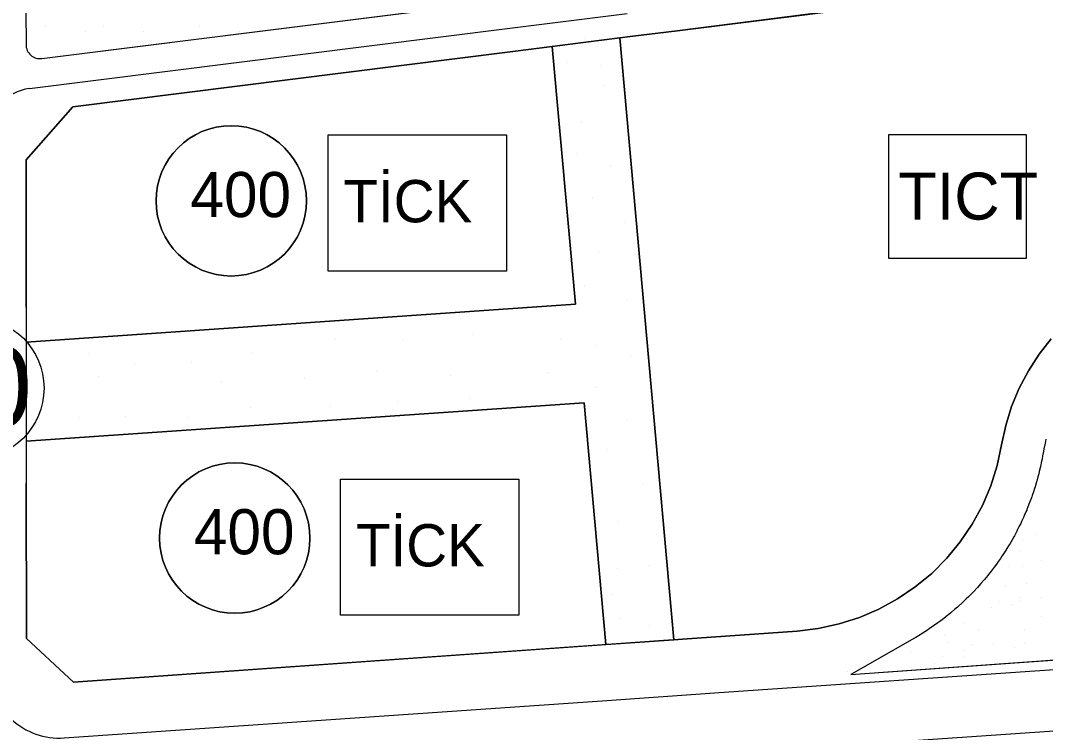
# Model space of a CAD drawing. Extents: x 419109 to 421295, y 4452223 to 4457798.
# Drawn here: x 419811.7 to 420029.7, y 4453711.7 to 4453863.1 of the extents above; entities that cross this region are included whole.
import ezdxf

# ---------------------------------------------------------------- set-up
doc = ezdxf.new("R2010")
doc.units = 0
for name, color, linetype in [('ADA', 7, 'Continuous'), ('ADAKENARI', 7, 'Continuous'), ('Default', 7, 'Continuous'), ('KALDIRIM', 7, 'Continuous'), ('KD_DAIRE', 7, 'Continuous'), ('KD_YGEN', 7, 'Continuous'), ('LJ_SEMBOL', 7, 'Continuous'), ('PL_AYA_PARK_DINLENME', 7, 'Continuous'), ('PL_TİCK', 7, 'Continuous'), ('PL_TURZM', 7, 'Continuous'), ('SM_TAKS', 7, 'Continuous'), ('TR_PARKALANI', 7, 'Continuous'), ('TR_TİCK', 7, 'Continuous'), ('TR_TİCT', 7, 'Continuous')]:
    doc.layers.add(name, color=color, linetype=linetype)

# ---------------------------------------------------------------- blocks, each defined once
blk = doc.blocks.new('POINT_DISPLAY')
at = {"layer": 'Default'}
blk.add_line((0, 0), (0, 0), dxfattribs=at)

msp = doc.modelspace()

# ---------------------------------------------------------------- linework, layer by layer
at = {"layer": 'ADA'}
for p, q in [((419924.74, 4453857.56), (419929.68, 4453802.74)), ((419950.66, 4453731.4), (419939.14, 4453859.37)), ((419931.56, 4453781.8), (419936.2, 4453730.38))]:
    msp.add_line(p, q, dxfattribs=at)
at = {"layer": 'ADAKENARI'}
for p, q in [((419951.35, 4453860.91), (420102.08, 4453879.87)), ((419816.2, 4453855), (419926.11, 4453868.82)), ((419812.82, 4453865.02), (419812.83, 4453857.97)), ((419941.35, 4453859.65), (419951.35, 4453860.91)), ((419915.81, 4453856.44), (419941.35, 4453859.65)), ((419822.76, 4453844.73), (419915.81, 4453856.44)), ((419812.84, 4453833.49), (419822.76, 4453844.73)), ((419812.87, 4453802.15), (419812.84, 4453833.49)), ((419812.87, 4453794.67), (419929.68, 4453802.74)), ((419812.87, 4453802.15), (419812.89, 4453764.59)), ((420030.92, 4453795.41), (420028.33, 4453792.11)), ((420028.33, 4453792.11), (420026.04, 4453788.58)), ((420026.04, 4453788.58), (420024.09, 4453784.87)), ((420024.09, 4453784.87), (420022.48, 4453780.99)), ((419812.89, 4453773.6), (419931.56, 4453781.8)), ((420022.48, 4453780.99), (420021.24, 4453776.98)), ((420021.24, 4453776.98), (420020.36, 4453772.87)), ((420020.36, 4453772.87), (420019.41, 4453768.44)), ((420019.41, 4453768.44), (420018.04, 4453764.12)), ((419812.92, 4453731.68), (419812.89, 4453764.59)), ((420018.04, 4453764.12), (420016.26, 4453759.95)), ((420016.26, 4453759.95), (420014.09, 4453755.97)), ((420014.09, 4453755.97), (420011.56, 4453752.21)), ((420011.56, 4453752.21), (420008.68, 4453748.72)), ((420008.68, 4453748.72), (420005.48, 4453745.51)), ((420005.48, 4453745.51), (420001.98, 4453742.62)), ((420001.98, 4453742.62), (419998.23, 4453740.08)), ((419998.23, 4453740.08), (419994.25, 4453737.91)), ((419994.25, 4453737.91), (419990.09, 4453736.13)), ((419990.09, 4453736.13), (419985.77, 4453734.75)), ((419976.84, 4453733.25), (419952.49, 4453731.53)), ((419981.34, 4453733.79), (419976.84, 4453733.25)), ((419985.77, 4453734.75), (419981.34, 4453733.79)), ((419812.92, 4453731.68), (419822.9, 4453722.39)), ((419952.49, 4453731.53), (419822.9, 4453722.39))]:
    msp.add_line(p, q, dxfattribs=at)
msp.add_arc((419815.83, 4453857.97), 3, 180.035, 277.1691, dxfattribs=at)
at = {"layer": 'KALDIRIM'}
for p, q in [((419915.19, 4453861.4), (419940.72, 4453864.61)), ((419813.59, 4453848.62), (419915.19, 4453861.4)), ((419960.3, 4453720.14), (420172.91, 4453734.83)), ((419988.28, 4453724.03), (420064.1, 4453729.39)), ((419961.31, 4453707.18), (420174.53, 4453721.91)), ((419820.96, 4453710.51), (419935.36, 4453718.41)), ((419935.36, 4453718.41), (419960.3, 4453720.14))]:
    msp.add_line(p, q, dxfattribs=at)
msp.add_lwpolyline([(420029.78, 4453774.04), (420029.68, 4453773.61), (420029.59, 4453773.22), (420029.44, 4453772.51), (420029.42, 4453772.38), (420029.26, 4453771.55), (420029.24, 4453771.4), (420029.08, 4453770.48), (420028.95, 4453769.82), (420028.87, 4453769.37), (420028.63, 4453768.27), (420028.62, 4453768.24), (420028.37, 4453767.17), (420028.25, 4453766.68), (420028.09, 4453766.07), (420027.83, 4453765.13), (420027.79, 4453764.98), (420027.46, 4453763.9), (420027.37, 4453763.59), (420027.12, 4453762.82), (420026.86, 4453762.07), (420026.75, 4453761.76), (420026.36, 4453760.69), (420026.31, 4453760.56), (420025.95, 4453759.64), (420025.72, 4453759.07), (420025.68, 4453758.97), (420025.52, 4453758.6), (420025.09, 4453757.59), (420025.07, 4453757.56), (420024.6, 4453756.53), (420024.41, 4453756.13), (420024.11, 4453755.52), (420023.69, 4453754.7), (420023.6, 4453754.51), (420023.06, 4453753.51), (420022.94, 4453753.28), (420022.51, 4453752.53), (420022.14, 4453751.89), (420021.94, 4453751.55), (420021.35, 4453750.59), (420021.3, 4453750.52), (420020.74, 4453749.64), (420020.5, 4453749.27), (420020.43, 4453749.17), (420020.11, 4453748.7), (420019.51, 4453747.85), (420019.46, 4453747.77), (420018.79, 4453746.86), (420018.56, 4453746.55), (420018.11, 4453745.96), (420017.58, 4453745.29), (420017.41, 4453745.08), (420016.69, 4453744.21), (420016.55, 4453744.05), (420015.95, 4453743.35), (420015.5, 4453742.84), (420015.2, 4453742.51), (420014.43, 4453741.68), (420014.41, 4453741.66), (420013.64, 4453740.87), (420013.28, 4453740.51), (420012.84, 4453740.08), (420012.12, 4453739.4), (420012.02, 4453739.3), (420011.18, 4453738.54), (420010.94, 4453738.32), (420010.33, 4453737.79), (420009.72, 4453737.27), (420009.47, 4453737.06), (420008.59, 4453736.35), (420008.47, 4453736.26), (420007.7, 4453735.66), (420007.2, 4453735.28), (420006.79, 4453734.98), (420005.89, 4453734.34), (420005.87, 4453734.33), (420004.94, 4453733.69), (420004.56, 4453733.44), (420003.99, 4453733.07), (420003.21, 4453732.58), (420003.04, 4453732.47), (420002.07, 4453731.89), (420001.83, 4453731.75), (419988.28, 4453724.03)], dxfattribs=at)
for centre, radius, start, end in [((419814.84, 4453838.7), 10, 97.1689, 180.0425), ((419819.92, 4453725.47), 15, 180.0425, 273.9541)]:
    msp.add_arc(centre, radius, start, end, dxfattribs=at)
at = {"layer": 'KD_DAIRE'}
msp.add_circle((419801.66, 4453784.89), 15, dxfattribs=at)
at = {"layer": 'LJ_SEMBOL'}
for points in [[(419877.07, 4453838.74), (419915.01, 4453838.74), (419915.01, 4453809.8), (419877.07, 4453809.8)], [(419996.37, 4453838.81), (420025.57, 4453838.81), (420025.57, 4453812.46), (419996.37, 4453812.46)], [(419879.75, 4453765.56), (419917.68, 4453765.56), (419917.68, 4453736.62), (419879.75, 4453736.62)]]:
    msp.add_lwpolyline(points, close=True, dxfattribs=at)
at = {"layer": 'PL_AYA_PARK_DINLENME'}
for points in [[(419816.2, 4453855), (419926.11, 4453868.82), (419942, 4453870.82), (419977.82, 4453875.32)], [(419812.82, 4453865.02), (419812.83, 4453857.97)], [(419936.2, 4453730.38), (419950.66, 4453731.4), (419939.14, 4453859.37), (419924.74, 4453857.56), (419929.68, 4453802.74), (419812.87, 4453794.67), (419812.89, 4453773.6), (419931.56, 4453781.8), (419936.2, 4453730.38)], [(420029.78, 4453774.04), (420029.68, 4453773.61), (420029.59, 4453773.22), (420029.44, 4453772.51), (420029.42, 4453772.38), (420029.26, 4453771.55), (420029.24, 4453771.4), (420029.08, 4453770.48), (420028.95, 4453769.82), (420028.87, 4453769.37), (420028.63, 4453768.27), (420028.62, 4453768.24), (420028.37, 4453767.17), (420028.25, 4453766.68), (420028.09, 4453766.07), (420027.83, 4453765.13), (420027.79, 4453764.98), (420027.46, 4453763.9), (420027.37, 4453763.59), (420027.12, 4453762.82), (420026.86, 4453762.07), (420026.75, 4453761.76), (420026.36, 4453760.69), (420026.31, 4453760.56), (420025.95, 4453759.64), (420025.72, 4453759.07), (420025.68, 4453758.97), (420025.52, 4453758.6), (420025.09, 4453757.59), (420025.07, 4453757.56), (420024.6, 4453756.53), (420024.41, 4453756.13), (420024.11, 4453755.52), (420023.69, 4453754.7), (420023.6, 4453754.51), (420023.06, 4453753.51), (420022.94, 4453753.28), (420022.51, 4453752.53), (420022.14, 4453751.89), (420021.94, 4453751.55), (420021.35, 4453750.59), (420021.3, 4453750.52), (420020.74, 4453749.64), (420020.5, 4453749.27), (420020.43, 4453749.17), (420020.11, 4453748.7), (420019.51, 4453747.85), (420019.46, 4453747.77), (420018.79, 4453746.86), (420018.56, 4453746.55), (420018.11, 4453745.96), (420017.58, 4453745.29), (420017.41, 4453745.08), (420016.69, 4453744.21), (420016.55, 4453744.05), (420015.95, 4453743.35), (420015.5, 4453742.84), (420015.2, 4453742.51), (420014.43, 4453741.68), (420014.41, 4453741.66), (420013.64, 4453740.87), (420013.28, 4453740.51), (420012.84, 4453740.08), (420012.12, 4453739.4), (420012.02, 4453739.3), (420011.18, 4453738.54), (420010.94, 4453738.32), (420010.33, 4453737.79), (420009.72, 4453737.27), (420009.47, 4453737.06), (420008.59, 4453736.35), (420008.47, 4453736.26), (420007.7, 4453735.66), (420007.2, 4453735.28), (420006.79, 4453734.98), (420005.89, 4453734.34), (420005.87, 4453734.33), (420004.94, 4453733.69), (420004.56, 4453733.44), (420003.99, 4453733.07), (420003.21, 4453732.58), (420003.04, 4453732.47), (420002.07, 4453731.89), (420001.83, 4453731.75)], [(420001.83, 4453731.75), (419988.28, 4453724.03), (420064.1, 4453729.39)]]:
    msp.add_lwpolyline(points, dxfattribs=at)
msp.add_arc((419815.83, 4453857.97), 3, 180.035, 277.1691, dxfattribs=at)
at = {"layer": 'PL_TİCK'}
for points in [[(419924.74, 4453857.56), (419915.81, 4453856.44), (419822.76, 4453844.73), (419812.84, 4453833.49), (419812.87, 4453802.15), (419812.87, 4453794.67), (419929.68, 4453802.74), (419924.74, 4453857.56)], [(419812.89, 4453773.6), (419812.89, 4453764.59), (419812.92, 4453731.68), (419822.9, 4453722.39), (419936.2, 4453730.38), (419931.56, 4453781.8), (419812.89, 4453773.6)]]:
    msp.add_lwpolyline(points, dxfattribs=at)
at = {"layer": 'PL_TURZM'}
for points in [[(420102.08, 4453879.87), (419979.2, 4453864.41), (419951.35, 4453860.91), (419941.35, 4453859.65), (419939.14, 4453859.37), (419950.66, 4453731.4)], [(419950.66, 4453731.4), (419952.49, 4453731.53), (419976.84, 4453733.25), (419981.34, 4453733.79), (419985.77, 4453734.75), (419990.09, 4453736.13), (419994.25, 4453737.91), (419998.23, 4453740.08), (420001.98, 4453742.62), (420005.48, 4453745.51), (420008.68, 4453748.72), (420011.56, 4453752.21), (420014.09, 4453755.97), (420016.26, 4453759.95), (420018.04, 4453764.12), (420019.41, 4453768.44), (420020.36, 4453772.87), (420021.24, 4453776.98), (420022.48, 4453780.99), (420024.09, 4453784.87), (420026.04, 4453788.58), (420028.33, 4453792.11), (420030.92, 4453795.41)]]:
    msp.add_lwpolyline(points, dxfattribs=at)
at = {"layer": 'SM_TAKS'}
for centre in [(419856.49, 4453824.73), (419857.23, 4453753.02)]:
    msp.add_circle(centre, 15.99, dxfattribs=at)
at = {"layer": 'TR_TİCK'}
for points in [[(419929.68, 4453802.74), (419924.74, 4453857.56), (419915.81, 4453856.44), (419822.76, 4453844.73), (419812.84, 4453833.49), (419812.87, 4453802.15), (419812.87, 4453794.67), (419929.68, 4453802.74)], [(419877.07, 4453809.8), (419877.07, 4453838.74), (419915.01, 4453838.74), (419915.01, 4453809.8), (419877.07, 4453809.8)], [(419812.89, 4453773.6), (419812.89, 4453764.59), (419812.92, 4453731.68), (419822.9, 4453722.39), (419936.2, 4453730.38), (419931.56, 4453781.8), (419812.89, 4453773.6)], [(419879.75, 4453736.62), (419879.75, 4453765.56), (419917.68, 4453765.56), (419917.68, 4453736.62), (419879.75, 4453736.62)]]:
    msp.add_lwpolyline(points, dxfattribs=at)
for centre, start, end in [((419856.49, 4453824.73), 0, 180), ((419856.49, 4453824.73), 180, 0), ((419857.23, 4453753.02), 0, 180), ((419857.23, 4453753.02), 180, 0)]:
    msp.add_arc(centre, 15.99, start, end, dxfattribs=at)
at = {"layer": 'TR_TİCT'}
for points in [[(420102.08, 4453879.87), (419979.2, 4453864.41), (419951.35, 4453860.91), (419941.35, 4453859.65), (419939.14, 4453859.37), (419950.66, 4453731.4)], [(419996.37, 4453812.46), (419996.37, 4453838.81), (420025.57, 4453838.81), (420025.57, 4453812.46), (419996.37, 4453812.46)], [(419950.66, 4453731.4), (419952.49, 4453731.53), (419976.84, 4453733.25), (419981.34, 4453733.79), (419985.77, 4453734.75), (419990.09, 4453736.13), (419994.25, 4453737.91), (419998.23, 4453740.08), (420001.98, 4453742.62), (420005.48, 4453745.51), (420008.68, 4453748.72), (420011.56, 4453752.21), (420014.09, 4453755.97), (420016.26, 4453759.95), (420018.04, 4453764.12), (420019.41, 4453768.44), (420020.36, 4453772.87), (420021.24, 4453776.98), (420022.48, 4453780.99), (420024.09, 4453784.87), (420026.04, 4453788.58), (420028.33, 4453792.11), (420030.92, 4453795.41)]]:
    msp.add_lwpolyline(points, dxfattribs=at)

# ---------------------------------------------------------------- block references
at = {"layer": 'TR_PARKALANI', "xscale": 0.1, "yscale": 0.10000000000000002}
for p in [(419816.99, 4453861.76), (419825.42, 4453860.71), (419829.4, 4453861.76), (419837.83, 4453860.71), (419849.71, 4453861.76), (419858.14, 4453860.71), (419931.59, 4453859.23), (419928.04, 4453854.23), (419934.99, 4453853.49), (419935.58, 4453849.2), (419931, 4453841.5), (419929.96, 4453834.84), (419937.06, 4453832.18), (419933.36, 4453825.52), (419940.17, 4453820.19), (419934.7, 4453813.83), (419931.59, 4453806.73), (419940.61, 4453803.47), (419878.76, 4453795.18), (419892.96, 4453795.18), (419907.76, 4453796.22), (419926.56, 4453795.33), (419815.49, 4453792.67), (419826.22, 4453792.23), (419860.7, 4453792.52), (419934.1, 4453794), (419835.99, 4453790.15), (419848.12, 4453790.45), (419941.5, 4453791.63), (419887.49, 4453788.53), (419923.89, 4453788.23), (419816.97, 4453787.19), (419828.29, 4453787.34), (419854.49, 4453786.31), (419872.1, 4453786.9), (419903.03, 4453787.64), (419934.25, 4453785.12), (419891.93, 4453782.01), (419907.17, 4453782.75), (419860.56, 4453780.83), (419877.57, 4453780.98), (419814.9, 4453776.91), (419824.3, 4453778.61), (419833.92, 4453778.91), (419847.09, 4453778.61), (419940.47, 4453778.02), (419936.47, 4453771.95), (420029.61, 4453771.94), (419944.02, 4453764.7), (419938.84, 4453756.56), (419946.98, 4453753.75), (420027.64, 4453753.84), (420024.8, 4453752.42), (420024.09, 4453750.06), (419938.69, 4453746.5), (419945.5, 4453747.24), (420021.73, 4453746.98), (420024.8, 4453746.98), (420028.84, 4453748.33), (420021.16, 4453742.73), (420025.65, 4453743.44), (419937.36, 4453741.02), (420024.38, 4453740.29), (420028.76, 4453740.44), (420018.18, 4453738.24), (420019.89, 4453739.58), (420022.67, 4453738.95), (420024.27, 4453739.73), (419939.14, 4453735.99), (420028.82, 4453736.35), (419945.35, 4453734.51), (420012.51, 4453734.93), (420015.49, 4453733.51), (420025.27, 4453733.51), (420008.25, 4453732.33), (420009.1, 4453730.91), (420012.51, 4453729.02), (420014.21, 4453730.36), (420018.6, 4453730.51), (420023.14, 4453729.73), (420025.27, 4453730.67), (420000.92, 4453728.78), (420007.83, 4453727.76), (420012.22, 4453727.91), (419987.66, 4453724.71), (420006.12, 4453726.42)]:
    msp.add_blockref('POINT_DISPLAY', p, dxfattribs=at)

# ---------------------------------------------------------------- texts
at = {"layer": 'KD_YGEN'}
msp.add_text('20', height=17, dxfattribs=at).set_placement((419788.81, 4453776.69))
at = {"layer": 'LJ_SEMBOL'}
for s, height, p in [('TİCK', 9, (419880.34, 4453820.16)), ('TICT', 10, (419998.39, 4453820.74)), ('TİCK', 9, (419883.01, 4453746.98))]:
    msp.add_text(s, height=height, dxfattribs=at).set_placement(p)
at = {"layer": 'SM_TAKS'}
for p in [(419847.8, 4453821.27), (419848.54, 4453749.57)]:
    msp.add_text('400', height=9.593, dxfattribs=at).set_placement(p)

doc.saveas('drawing.dxf')
